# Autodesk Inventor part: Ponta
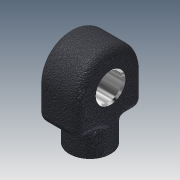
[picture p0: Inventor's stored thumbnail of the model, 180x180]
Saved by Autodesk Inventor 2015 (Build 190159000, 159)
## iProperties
Created: 2015-04
Part Number: Ponta
Material: Iron, Cast
Document SubType Name: Modeling
Designer: TREINA6
Density: 7.15 g/cm^3
Appearance: Iron - Cast
Author: TREINA6
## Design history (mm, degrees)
sketch "Sketch1"
  geometry: C1 r 12.5 at (0, 0); 1 further point
  constraints: 1 centre point, 1 coincident
  dimensions: "d0" = 25 diameter of C1
extrude "Extrusion1" new body sketch "Sketch1" distance "d1" = 15; taper "d2" = 0 deg
sketch "Sketch2"
  geometry: L1 (-12.5, 20)-(12.5, 20); L2 (12.5, 20)-(12.5, -20); L3 (12.5, -20)-(-12.5, -20); L4 (-12.5, -20)-(-12.5, 20); 3 further points
  constraints: 8 end point, 2 midpoint, 2 parallel, 1 horizontal, 1 horizontal alignment, 1 perpendicular, 1 vertical alignment
  dimensions: "d3" = 40 distance of L1.end L2.end; "d4" = 25 distance of L2.end L3.end
extrude "Extrusion2" join sketch "Sketch2" distance "d5" = 40; taper "d6" = 0 deg
fillet "Fillet1"
hole "Hole1" diameter "d9" = 16; stored, may be unused: countersink angle "d13" = 90 deg, drill point angle "d15" = 118 deg; dims "d7" = 10, "d8" = 10, "d10" = 6, "d11" = 4, "d12" = 2, "d14" = 8
fillet "Fillet2" dims "d16" = 5
fillet "Fillet3" dims "d17" = 5
hole "Hole2" diameter "d20" = 17.294; stored, may be unused: countersink angle "d24" = 90 deg, drill point angle "d26" = 118 deg; dims "d18" = 10, "d19" = 10, "d21" = 40, "d22" = 4, "d23" = 2, "d25" = 19.7
chamfer "Chamfer1" distance "d27" = 1; stored, may be unused: second distance "d28" = 2, angle "d29" = 45 deg
body "Solid1"
